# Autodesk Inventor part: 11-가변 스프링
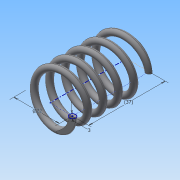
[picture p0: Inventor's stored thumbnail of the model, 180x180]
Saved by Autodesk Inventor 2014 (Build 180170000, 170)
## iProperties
Created: 2015-09
Part Number: 11-가변 스프링
Material: 강철, 탄소
Document SubType Name: Modeling
Designer: study
Density: 7.87 g/cm^3
Appearance: 반연마
Mass: 18.6318 g
Surface Area: 32.4192 cm^2
Volume: 2.36745 cm^3
Author: study
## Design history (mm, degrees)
sketch "스케치1"
  geometry: L1 (0, 0)-(11, 0); L2 (11, 0)-(11, 25.358); L3 (11, 25.358)-(0, 25.358); L4 (0, 25.358)-(0, 0); C1 r 1.5 at (11, 0)
  constraints: 8 end point, 2 parallel, 1 centre point, 1 coincident, 1 horizontal, 1 perpendicular
  dimensions: "d0" = 25.35829 distance of L1.end L2.end (derived); "d1" = 22 diameter of L2 L4; "d2" = 3 diameter of C1
feature "코일1" sketch "스케치1" pitch "d3" = 10; turns "d5" = 5; dims "d4" = 25.35829 (= d0), "d6" = 0, angle "d7" = 90 deg, angle "d8" = 90 deg, "d9" = 0, "d10" = 0
node "작업 평면1"
sketch "스케치2"
  geometry: L1 (-12.5, 0)-(-9.5, 0) reference; 1 further point
  constraints: 1 horizontal alignment
extrude "돌출1" cut sketch "스케치2" stored distance "d12" = 10; taper "d13" = 0 deg
node "작업 평면2"
sketch "스케치3"
  geometry: L1 (-9.5, 0)-(-12.5, 0) reference; 1 further point
  constraints: 1 horizontal alignment
extrude "돌출2" cut sketch "스케치3" stored distance "d15" = 10; taper "d16" = 0 deg
node "솔리드1"
node "절단 모서리 투영1"
node "절단 모서리 투영2"
other parameters: "d11" = 0, "d14" = 25.35829 (= d0)
